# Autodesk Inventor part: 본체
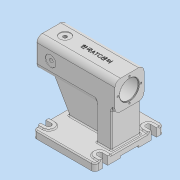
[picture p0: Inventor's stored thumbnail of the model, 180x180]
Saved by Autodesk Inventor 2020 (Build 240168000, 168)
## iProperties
Created: 2024-07
Part Number: 본체
Material: 일반
Document SubType Name: Modeling
Designer: oem
Density: 1 g/cm^3
Appearance: 기본값
Author: oem
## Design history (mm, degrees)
sketch "스케치1"
  geometry: L1 (85, -95)-(-85, -95); L2 (-85, -95)-(-85, 95); L3 (-85, 95)-(85, 95); L4 (85, 95)-(85, -95); 3 further points
  constraints: 8 end point, 2 midpoint, 2 parallel, 1 horizontal, 1 horizontal alignment, 1 perpendicular, 1 vertical alignment
  dimensions: "d0" = 170 distance of L1.start L1.end; "d1" = 190 distance of L1.end L2.end
extrude "돌출1" new body sketch "스케치1" distance "d2" = 20; taper "d3" = 0 deg
sketch "스케치2"
  geometry: L1 (0, 0)-(190, 0) reference; L2 (55, 190)-(135, 190); L3 (135, 190)-(135, 110); L4 (135, 110)-(55, 110); L5 (55, 110)-(55, 190); 4 further points
  constraints: 8 end point, 3 midpoint, 2 parallel, 1 horizontal, 1 perpendicular, 1 vertical alignment
  dimensions: "d4" = 80 distance of L2.end L3.end; "d5" = 80 distance of L2.start L2.end; "d6" = 150 distance from line of L1 point (55, 150)
extrude "돌출2" join sketch "스케치2" distance "d7" = 217; taper "d8" = 0 deg
sketch "스케치3"
  geometry: L1 (85, -95)-(85, 95) reference; L2 (35, -40)-(75, -40); L3 (75, -40)-(75, 40); L4 (75, 40)-(35, 40); L5 (35, 40)-(35, -40); 2 further points
  constraints: 8 end point, 2 parallel, 1 horizontal, 1 horizontal alignment, 1 midpoint, 1 perpendicular
  dimensions: "d9" = 40 distance of L3.end L4.end; "d10" = 80 distance of L2.end L3.end; "d11" = 10 distance between parallel lines of L1 L3
extrude "돌출3" join sketch "스케치3" stored distance "d12" = 217; taper "d13" = 0 deg
node "작업 평면1"
sketch "스케치4"
  geometry: L1 (-50, 0)-(-217, 0) reference; L2 (-202, 0)-(-150.038, -90); L3 (0, -90)-(-170, -90) reference; L4 (-10, -90)-(-10, 0) reference; L5 (-50, -90)-(-10, -90) reference; L6 (-50, -90)-(-50, 0) reference; L7 (-50, 0)-(-217, 0) reference; L8 (-217, 80)-(-217, 0) reference; L9 (0, 80)-(-217, 80) reference; L10 (0, 0)-(0, 80) reference; L11 (0, 0)-(-10, 0) reference; L12 (0, -110)-(-170, -110) reference; L13 (-170, -110)-(-170, -90) reference; L14 (0, -90)-(-170, -90) reference; L15 (0, -110)-(0, -90) reference; 3 further points
  constraints: 2 end point, 2 point on line
  dimensions: "d15" = 15 distance of L1.end L2.start; "d16" = 120 deg angle of L3 L2
extrude "돌출4" join sketch "스케치4" stored distance "d17" = 30; taper "d18" = 0 deg
sketch "스케치5"
  geometry: L1 (-132, 150)-(85, 150); L2 (85, 176)-(-127, 176); L3 (-127, 176)-(-127, 170.5); L4 (-127, 170.5)-(-132, 170.5); L5 (-132, 190)-(-132, 110) reference; L6 (85, 110)-(85, 190) reference; 1 further point
  constraints: 8 end point, 2 midpoint, 2 perpendicular, 2 point on line, 1 horizontal
  dimensions: "d22" = 212 distance of L2.start L2.end; "d25" = 41 diameter of L4 L1; "d26" = 52 diameter of L2 L1
revolve "회전1" sketch "스케치5" stored, may be unused: angle "d27" = 90 deg
sketch "스케치6"
  geometry: L1 (0, 0)-(190, 0) reference; L2 (70, 0)-(120, 0); L3 (120, 0)-(120, 5); L4 (120, 5)-(70, 5); L5 (70, 5)-(70, 0); 5 further points
  constraints: 8 end point, 2 midpoint, 2 parallel, 1 collinear, 1 horizontal, 1 perpendicular, 1 vertical alignment
  dimensions: "d31" = 50 distance of L2.start L2.end; "d32" = 5 distance of L4.end L2.start
extrude "돌출5" cut sketch "스케치6" distance "d33" = 184.25; taper "d34" = 0 deg
sketch "스케치7" dims "d37" = 30
  geometry: L1 (85, -95)-(85, 95) reference; L2 (70, -67)-(70, 67); L3 (85, -82)-(70, -82); L4 (85, 52)-(70, 52); L5 (85, -52)-(70, -52); L6 (85, 82)-(70, 82); L7 (-85, -95)-(85, -95) reference; L8 (0, -95)-(0, 115.42); L9 (-75, 40)-(-75, -40); L10 (-70, -67)-(-70, 67); L11 (-85, -95)-(-85, 95); L12 (-85, -52)-(-70, -52); L13 (-85, -82)-(-70, -82); L14 (-85, 52)-(-70, 52); L15 (-85, 82)-(-70, 82); A1 r 15 centre (70, -67) between (70, -82) and (70, -52); A2 r 15 centre (-70, -67) between (-70, -82) and (-70, -52); 9 further points
  constraints: 26 end point, 14 symmetric about line, 10 point on line, 6 horizontal, 4 point on circle, 3 midpoint, 2 centre point, 2 tangent, 2 vertical, 1 horizontal alignment, 7 other
  dimensions: "d35" = 30 diameter of A1; "d36" = 15 distance from line of L1 L2.start; "d38" = 15 distance from line of L1 L2.end; "d39" = 134 distance of L2.start L2.end
extrude "돌출6" join sketch "스케치7" distance "d40" = 3; taper "d41" = 0 deg
sketch "스케치8"
  geometry: L1 (85, 82)-(70, 82) reference; L2 (70, 52)-(85, 52) reference; L3 (85, 52)-(85, 82) reference; L4 (85, 60)-(70, 60); L5 (70, 74)-(85, 74); L6 (70, -82)-(85, -82) reference; L7 (70, -82)-(85, -82) reference; L8 (85, -82)-(85, -52) reference; L9 (85, -52)-(70, -52) reference; L10 (70, -74)-(85, -74); L11 (85, -60)-(70, -60); L12 (-85, -95)-(85, -95) reference; L13 (0, -95)-(0, 108.744); L14 (-85, 82)-(-70, 82); L15 (-70, 52)-(-85, 52); L16 (-85, 60)-(-70, 60); L17 (-70, 74)-(-85, 74); L18 (-85, 52)-(-85, 82); L19 (-85, -52)-(-70, -52); L20 (-85, -60)-(-70, -60); L21 (-70, -74)-(-85, -74); L22 (-85, -82)-(-85, -52); L23 (-70, -82)-(-85, -82); L24 (-70, -82)-(-85, -82); A1 r 15 centre (70, 67) between (70, 82) and (70, 52) reference; A2 r 7 centre (70, 67) between (70, 74) and (70, 60); A3 r 15 centre (70, -67) between (70, -52) and (70, -82) reference; A4 r 15 centre (70, -67) between (70, -52) and (70, -82) reference; A5 r 7 centre (70, -67) between (70, -60) and (70, -74); A6 r 15 centre (-70, 67) between (-70, 52) and (-70, 82); A7 r 7 centre (-70, 67) between (-70, 60) and (-70, 74); A8 r 7 centre (-70, -67) between (-70, -74) and (-70, -60); A9 r 15 centre (-70, -67) between (-70, -82) and (-70, -52); A10 r 15 centre (-70, -67) between (-70, -82) and (-70, -52); 1 further point
  constraints: 32 end point, 22 symmetric about line, 14 point on circle, 8 point on line, 7 centre point, 1 midpoint, 1 perpendicular, 1 vertical, 8 other
  dimensions: "d42" = 14 distance between parallel lines of L5 L4; "d43" = 14 distance of L10.end L11.start
extrude "돌출7" cut sketch "스케치8" stored distance "d44" = 3; taper "d45" = 0 deg
sketch "스케치9"
  geometry: L1 (0, 80)-(0, 0) reference; L2 (0, 40)-(-177, 40); 2 further points
  constraints: 2 end point, 2 midpoint, 1 coincident, 1 horizontal
  dimensions: "d46" = 177 distance of L2.start L2.end
hole "구멍1" sketch "스케치9" at (-177, 40) diameter "d47" = 10.106; stored, may be unused: countersink angle "d51" = 90 deg, drill point angle "d53" = 118 deg; dims "d48" = 24, "d49" = 30, "d50" = 2, "d52" = 32.3
sketch "스케치10"
  geometry: L1 (0, -12)-(0, 92) reference; L2 (0, 40)-(-177, 40); 1 further point
  constraints: 2 end point, 1 horizontal, 1 midpoint
  dimensions: "d54" = 177 distance of L2.start L2.end
hole "구멍2" sketch "스케치10" at (-177, 40) diameter "d55" = 10.106; stored, may be unused: countersink angle "d59" = 90 deg, drill point angle "d61" = 118 deg; dims "d56" = 24, "d57" = 30, "d58" = 2, "d60" = 32.3
fillet "모깎기1" dims "d62" = 15
fillet "모깎기2" dims "d63" = 3
fillet "모깎기3" dims "d64" = 3
fillet "모깎기4" dims "d65" = 3
fillet "모깎기5" dims "d66" = 3
fillet "모깎기6" dims "d67" = 3
fillet "모깎기7" dims "d68" = 3
fillet "모깎기8" dims "d69" = 3
sketch "스케치11"
  geometry: L1 (95, 150)-(95, 182); C1 r 27 at (95, 150) reference; 1 further point
  constraints: 2 end point, 1 vertical
  dimensions: "d70" = 32 distance of L1.start L1.end
hole "구멍3" sketch "스케치11" at (95, 182) diameter "d71" = 4.917; stored, may be unused: countersink angle "d75" = 90 deg, drill point angle "d77" = 118 deg; dims "d72" = 12, "d73" = 30, "d74" = 2, "d76" = 14
fillet "모깎기9" dims "d81" = 3
fillet "모깎기10" dims "d82" = 10
fillet "모깎기11" dims "d83" = 3
sketch "스케치12"
  geometry: L1 (0, 104)-(0, 110) reference; 2 further points
  constraints: 1 horizontal alignment, 1 other
  dimensions: "d84" = 90 distance from line of L1 point (-90, 25)
feature "엠보싱1" sketch "스케치12" dims "d0" = 170, "d1" = 190, "d85" = 0.5, "d86" = 0
sketch "스케치13"
  geometry: L1 (85, 176)-(-127, 176) reference; L2 (83, 176)-(85, 177.155); L3 (85, 190)-(85, 175) reference; L4 (50.104, 150)-(120.269, 150); L5 (85, 125)-(85, 175) reference; L6 (-129, 190)-(-129, 175) reference; L7 (-129, 190)-(85, 190) reference; L8 (85, 190)-(85, 175) reference; L9 (85, 175)-(-129, 175) reference; 3 further points
  constraints: 4 end point, 2 midpoint, 2 point on line, 1 horizontal, 1 horizontal alignment
  dimensions: "d87" = 2 horizontal distance of L2.start L2.end; "d88" = 30 deg angle of L1 L2
revolve "회전2" sketch "스케치13" stored, may be unused: angle "d89" = 90 deg
fillet "모깎기12" dims "d90" = 1
fillet "모깎기13" dims "d91" = 2
node "솔리드1"
mirror "미러1"
pattern_circular "원형 패턴1" dims angle "d79" = 360 deg
node "투영된 루프1"
node "투영된 루프2"
node "투영된 루프3"
node "투영된 루프4"
feature "A9D066F2-1C7D-4E18-AEED-F7BC21143FA4" dims "d47" = 10.106, "d48" = 24, "d49" = 30, "d50" = 2, "d51" = 90 deg, "d52" = 32.3, "d53" = 118 deg
other parameters: "d19" = 41, "d20" = 52
